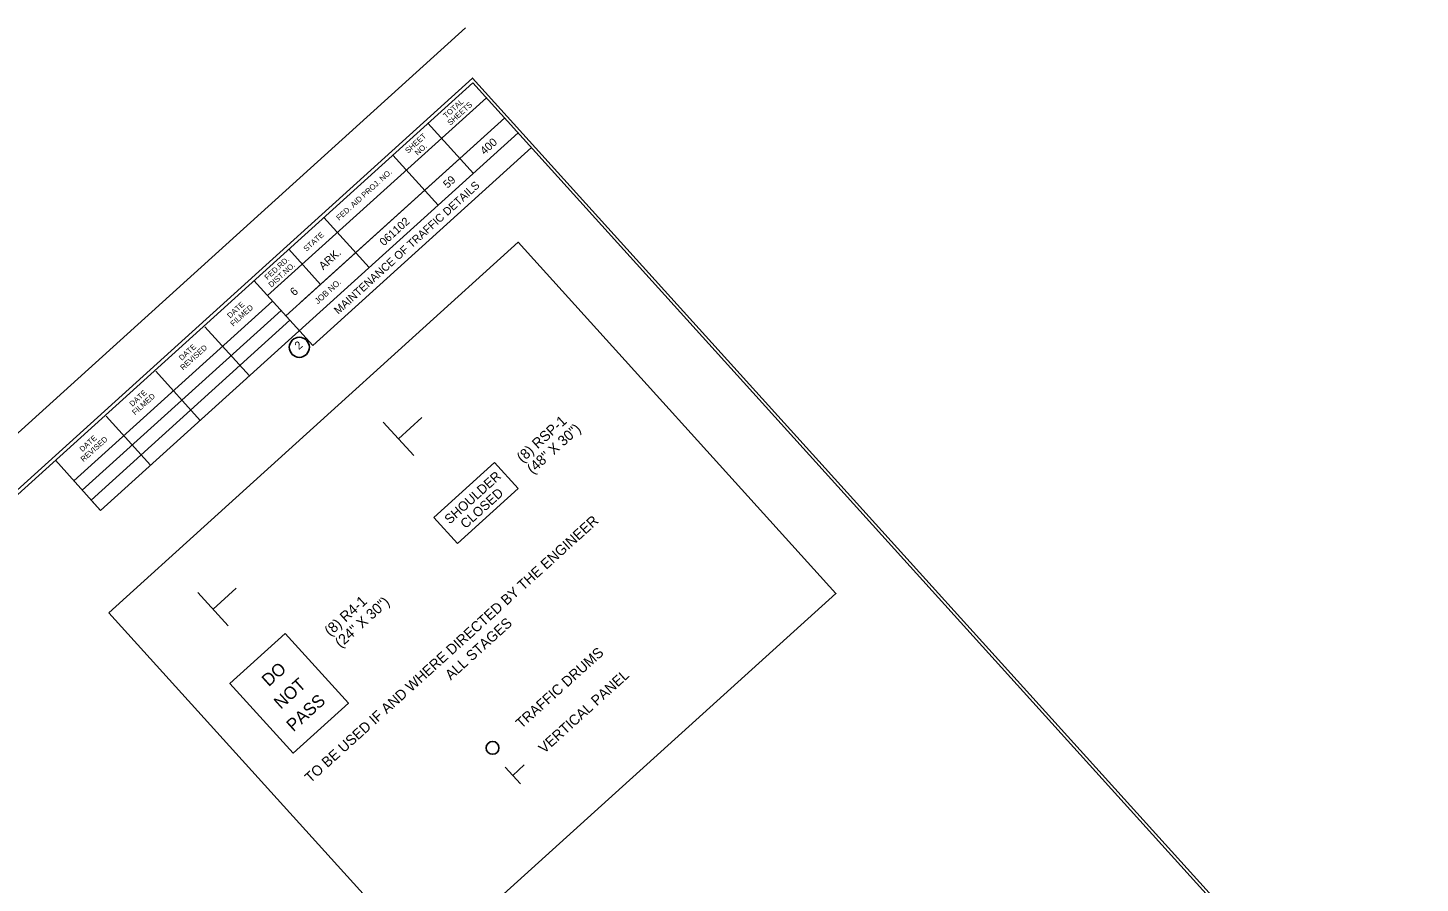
# Model space of a CAD drawing. Extents: x 1307930 to 1312775, y 238372 to 242903.
# Drawn here: x 1308915 to 1309932, y 239743 to 240368 of the extents above; entities that cross this region are included whole.
import ezdxf

# ---------------------------------------------------------------- set-up
doc = ezdxf.new("R2010")
doc.units = 0
for name, color, linetype in [('R_Border', 7, 'Continuous'), ('R_Draft', 7, 'Continuous'), ('R_Drive', 7, 'Continuous'), ('R_MOT', 7, 'Continuous'), ('R_No Plot', 7, 'Continuous')]:
    doc.layers.add(name, color=color, linetype=linetype)

msp = doc.modelspace()

# ---------------------------------------------------------------- linework, layer by layer
at = {"layer": 'R_Border'}
for p, q in [((1309234.8, 240368.2), (1307929.6, 239187.5)), ((1308067.7, 239267.6), (1309240.2, 240328.1)), ((1309929.3, 239566.2), (1309240.2, 240328.1)), ((1309250.1, 240317.1), (1309090.2, 240172.6)), ((1309250, 240317.3), (1309250, 240317.3)), ((1309263.5, 240302.4), (1309103.6, 240157.8)), ((1309114.5, 240167.7), (1309263.5, 240302.4)), ((1309207.4, 240298.6), (1309240.6, 240261.9)), ((1309273.3, 240291.5), (1308968.2, 240015.6)), ((1309123.2, 240136.1), (1309283.1, 240280.7)), ((1309181.7, 240275.3), (1309214.8, 240238.7)), ((1309131.4, 240229.7), (1309164.5, 240193.1)), ((1309105.7, 240206.5), (1309128.9, 240180.7)), ((1309080.2, 240183.5), (1309123.2, 240136.1)), ((1308948.5, 240037.2), (1309093.7, 240168.6)), ((1308954.8, 240030.4), (1309100, 240161.7)), ((1308961.3, 240023.2), (1309106.5, 240154.6)), ((1309076.9, 240113.9), (1309044.4, 240149.8)), ((1309041, 240081.3), (1309008.5, 240117.3)), ((1309004.7, 240048.6), (1308972.3, 240084.6)), ((1308968.2, 240015.6), (1308935.1, 240052.3)), ((1308968.2, 240015.6), (1308961.3, 240023.2))]:
    msp.add_line(p, q, dxfattribs=at)
msp.add_circle((1309113.4, 240134.8), 7.33, dxfattribs=at)
at = {"layer": 'R_Draft'}
msp.add_lwpolyline([(1308974.2, 239940.9), (1309273.4, 240211.5), (1309505.5, 239955), (1309206.3, 239684.4)], close=True, dxfattribs=at)
at = {"layer": 'R_MOT'}
for p, q in [((1309197, 240055.7), (1309174.7, 240080.1)), ((1309185.9, 240067.9), (1309202.9, 240083.4)), ((1309256.1, 240050.6), (1309211.8, 240010.5)), ((1309273.2, 240031.7), (1309256.1, 240050.6)), ((1309273.2, 240031.7), (1309228.9, 239991.5)), ((1309228.9, 239991.5), (1309211.8, 240010.5)), ((1309050.3, 239943.4), (1309067.3, 239958.9)), ((1309061.4, 239931.2), (1309039.1, 239955.7)), ((1309274.9, 239815.8), (1309263.7, 239828.1)), ((1309269.3, 239821.9), (1309277.8, 239829.7))]:
    msp.add_line(p, q, dxfattribs=at)
msp.add_lwpolyline([(1309103.1, 239925.8), (1309149.2, 239874.8), (1309108.8, 239838.3), (1309062.7, 239889.2)], close=True, dxfattribs=at)
msp.add_circle((1309254.6, 239842.1), 4.69, dxfattribs=at)
at = {"layer": 'R_No Plot'}
msp.add_lwpolyline([(1308757.1, 238502.4), (1309932.5, 239565.7), (1309239.9, 240331.5), (1308064.4, 239268.1)], close=True, dxfattribs=at)

# ---------------------------------------------------------------- texts
at = {"layer": 'R_Border'}
for s, height, rotation, p in [('TOTAL', 4, 42.1303, (1309220.7, 240301.8)), ('SHEETS', 4, 42.1303, (1309223.8, 240296.7)), ('SHEET', 4, 42.1303, (1309192.9, 240276.3)), ('NO.', 4, 42.1303, (1309199.9, 240274.7)), ('400', 5.89, 42.1338, (1309248.8, 240275.1)), ('FED. AID PROJ. NO.', 4, 42.1303, (1309142.5, 240227.2)), ('MAINTENANCE OF TRAFFIC DETAILS', 5.85, 42.1303, (1309141.9, 240158.5)), ('59', 5.85, 42.1338, (1309221.7, 240250.6)), ('061102', 5.85, 42.1303, (1309175.2, 240208.5)), ('STATE', 4, 42.1303, (1309118.6, 240204.5)), ('ARK.', 5.86, 42.1303, (1309130.9, 240191)), ('FED.RD.', 4, 42.1303, (1309090.1, 240183.7)), ('DIST.NO.', 4, 42.1303, (1309093, 240178.3)), ('JOB NO.', 4.4, 42.1303, (1309127, 240166.1)), ('6', 5.86, 42.1303, (1309109.8, 240172)), ('DATE', 4, 42.1303, (1309062.8, 240155.7)), ('FILMED', 4, 42.1303, (1309065.1, 240149.8)), ('DATE', 4, 42.1303, (1309027.5, 240124.8)), ('REVISED', 4, 42.1303, (1309028.5, 240117.8)), ('2', 5.86, 42.1303, (1309113.1, 240132.7)), ('DATE', 4, 42.1303, (1308991.4, 240091.2)), ('FILMED', 4, 42.1303, (1308993.4, 240085)), ('DATE', 4, 42.1303, (1308954.9, 240058.1)), ('REVISED', 4, 42.1303, (1308955.7, 240050.8))]:
    msp.add_text(s, height=height, rotation=rotation, dxfattribs=at).set_placement(p)
at = {"layer": 'R_Drive'}
for s, p in [('TRAFFIC DRUMS', (1309275.7, 239855.8)), ('VERTICAL PANEL', (1309292.3, 239837.6))]:
    msp.add_text(s, height=7.5, rotation=42.132, dxfattribs=at).set_placement(p)
at = {"layer": 'R_MOT'}
for s, height, p in [('(8) RSP-1', 7.5, (1309276.4, 240050.1)), ('(48" X 30")', 7.5, (1309283.9, 240041.8)), ('SHOULDER', 6.93, (1309223.3, 240005.2)), ('CLOSED', 6.93, (1309234.9, 240001.9)), ('TO BE USED IF AND WHERE DIRECTED BY THE ENGINEER', 7.5, (1309121.5, 239816.1)), ('(8) R4-1', 7.6, (1309135.9, 239923.3)), ('(24" X 30")', 7.605, (1309143.6, 239914.8)), ('ALL STAGES', 7.5, (1309224.1, 239891.2)), ('DO', 9.14, (1309091, 239886.4)), ('NOT', 9.14, (1309099.9, 239869.9)), ('PASS', 9.14, (1309109, 239853.5))]:
    msp.add_text(s, height=height, rotation=42.132, dxfattribs=at).set_placement(p)

doc.saveas('drawing.dxf')
